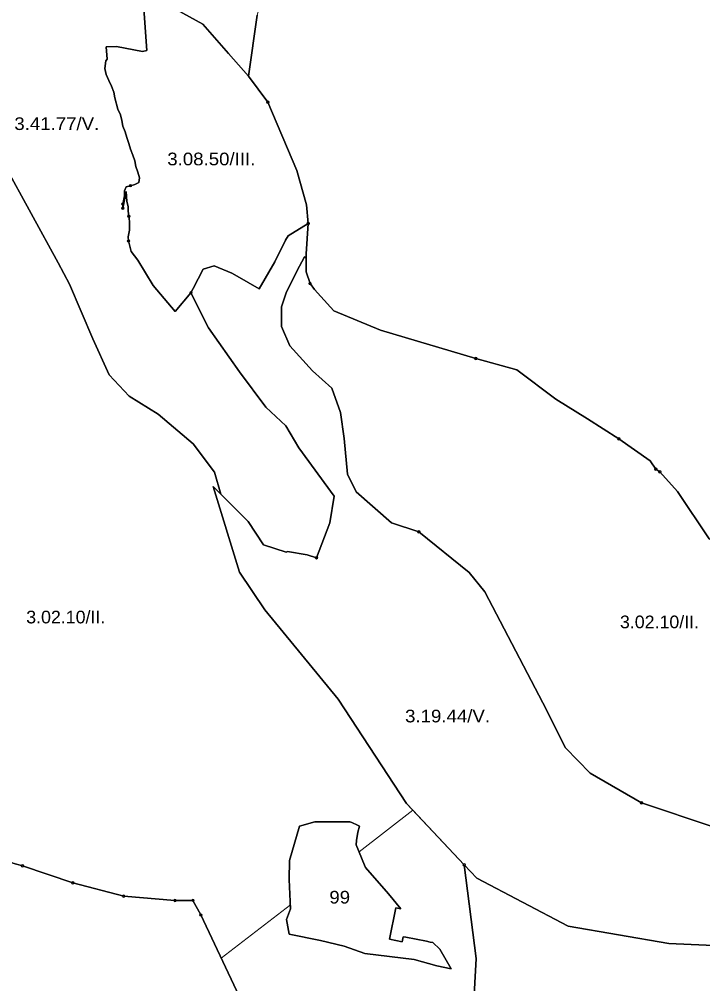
# Model space of a CAD drawing. Extents: x -650455 to -642254, y -1075222 to -1066610.
# Drawn here: x -645923 to -645383, y -1070807 to -1070045 of the extents above; entities that cross this region are included whole.
import ezdxf
from ezdxf.enums import TextEntityAlignment as Align

# ---------------------------------------------------------------- set-up
doc = ezdxf.new("R2010")
doc.units = 0
doc.header["$LTSCALE"] = 4
doc.header["$PDMODE"] = 32
doc.header["$PDSIZE"] = 2
for name, color, linetype, lineweight in [('1', 7, 'Continuous', 25), ('11', 7, 'Continuous', 13), ('12', 7, 'Continuous', 13), ('13', 7, 'Continuous', 13), ('15', 7, 'Continuous', 13), ('16', 7, 'Continuous', 13)]:
    doc.layers.add(name, color=color, linetype=linetype, lineweight=lineweight)
doc.layers.add('2', color=7, linetype='Continuous')

msp = doc.modelspace()

# ---------------------------------------------------------------- linework, layer by layer
at = {"layer": '1'}
for points in [[(-645827.805, -1070170.331), (-645829.232, -1070165.834), (-645830.719, -1070161.367), (-645831.596, -1070156.856), (-645833.216, -1070152.24), (-645834.881, -1070147.654), (-645836.323, -1070143.068), (-645837.765, -1070138.483), (-645839.206, -1070133.897), (-645841.079, -1070129.341), (-645841.912, -1070124.948), (-645842.729, -1070120.556), (-645844.914, -1070115.94), (-645847.337, -1070107.036), (-645848.229, -1070102.643), (-645850.013, -1070097.968), (-645852.064, -1070093.293), (-645854.131, -1070088.618), (-645855.32, -1070084.018), (-645854.309, -1070077.93), (-645853.462, -1070076.604), (-645854.242, -1070066.719), (-645845.918, -1070066.459), (-645825.452, -1070070.498), (-645821.972, -1070069.724), (-645825.17, -1070025.403)], [(-645825.17, -1070025.403), (-645821.972, -1070069.724), (-645825.452, -1070070.498), (-645845.918, -1070066.459), (-645854.242, -1070066.719), (-645853.462, -1070076.604), (-645854.309, -1070077.93), (-645855.32, -1070084.018), (-645854.131, -1070088.618), (-645852.064, -1070093.293), (-645850.013, -1070097.968), (-645848.229, -1070102.643), (-645847.337, -1070107.036), (-645844.914, -1070115.94), (-645842.729, -1070120.556)], [(-645817.043, -1070027.048), (-645777.762, -1070048.899), (-645757.472, -1070072.051), (-645741.915, -1070090.098)], [(-645735.031, -1070041.903), (-645741.915, -1070090.098), (-645757.472, -1070072.051), (-645777.762, -1070048.899), (-645817.043, -1070027.048)], [(-645474.208, -1070360.748), (-645499.088, -1070345.198), (-645530.032, -1070322.029), (-645562.376, -1070313.01), (-645637.482, -1070290.618), (-645674.491, -1070275.223), (-645677.134, -1070272.424), (-645689.807, -1070258.381), (-645693.219, -1070253.691), (-645696.21, -1070244.446), (-645696.21, -1070233.478), (-645696.21, -1070230.279), (-645694.628, -1070206.315), (-645696, -1070191.501), (-645703.5, -1070164.501), (-645726.5, -1070110.501), (-645741.915, -1070090.098), (-645735.031, -1070041.903)], [(-645741.915, -1070090.098), (-645726.5, -1070110.501), (-645703.5, -1070164.501), (-645696, -1070191.501), (-645694.628, -1070206.315), (-645710.517, -1070216.036), (-645712.468, -1070219.418), (-645721.12, -1070236.652), (-645733.239, -1070257.86), (-645750.708, -1070248.033), (-645754.87, -1070245.692), (-645768.918, -1070239.709), (-645777.502, -1070242.31), (-645785.567, -1070257.658), (-645787.196, -1070260.996), (-645799.614, -1070275.867), (-645817.043, -1070255.317), (-645829.113, -1070235.357), (-645831.774, -1070231.886), (-645834.45, -1070228.415), (-645835.52, -1070224.275), (-645836.59, -1070220.135), (-645836.754, -1070216.783), (-645836.218, -1070214.145), (-645835.683, -1070211.506), (-645835.698, -1070204.743), (-645836.248, -1070200.618), (-645836.798, -1070196.493), (-645836.694, -1070192.948), (-645837.839, -1070188.926), (-645838.285, -1070181.137), (-645841.065, -1070194.285), (-645841.065, -1070190.985), (-645839.771, -1070184.475), (-645839.593, -1070180.632), (-645838.3, -1070177.339), (-645834.881, -1070176.492), (-645831.462, -1070175.645), (-645828.37, -1070173.935), (-645827.805, -1070170.331)], [(-645842.729, -1070120.556), (-645841.912, -1070124.948), (-645841.079, -1070129.341), (-645839.206, -1070133.897), (-645837.765, -1070138.483), (-645836.323, -1070143.068), (-645834.881, -1070147.654), (-645833.216, -1070152.24), (-645831.596, -1070156.856), (-645830.719, -1070161.367), (-645829.232, -1070165.834), (-645827.805, -1070170.331), (-645828.37, -1070173.935), (-645831.462, -1070175.645), (-645834.881, -1070176.492), (-645838.3, -1070177.339), (-645839.593, -1070180.632), (-645839.771, -1070184.475), (-645841.065, -1070190.985), (-645841.065, -1070194.285), (-645838.285, -1070181.137), (-645837.839, -1070188.926), (-645836.694, -1070192.948), (-645836.798, -1070196.493), (-645836.248, -1070200.618), (-645835.698, -1070204.743), (-645835.683, -1070211.506), (-645836.218, -1070214.145), (-645836.754, -1070216.783), (-645836.59, -1070220.135), (-645835.52, -1070224.275), (-645834.45, -1070228.415), (-645831.774, -1070231.886), (-645829.113, -1070235.357), (-645817.043, -1070255.317), (-645799.614, -1070275.867), (-645787.196, -1070260.996), (-645773.285, -1070288.817), (-645748.941, -1070323.593), (-645728.075, -1070351.415)], [(-645937.054, -1070142.706), (-645934.808, -1070159.546), (-645892.146, -1070237.292), (-645883.165, -1070254.133), (-645864.64, -1070297.356), (-645851.729, -1070325.985), (-645836.012, -1070342.825), (-645812.997, -1070356.859), (-645785.491, -1070380.435), (-645768.65, -1070402.889), (-645763.626, -1070420.193)], [(-645728.075, -1070351.415), (-645712.426, -1070366.195), (-645701.993, -1070383.583), (-645674.172, -1070421.837), (-645677.649, -1070442.703), (-645688.022, -1070470.362), (-645695.5, -1070468.001), (-645711, -1070465.5), (-645712.054, -1070466.012), (-645729.814, -1070460.091), (-645741.986, -1070441.834), (-645763.626, -1070420.193), (-645768.65, -1070402.889), (-645785.491, -1070380.435), (-645812.997, -1070356.859), (-645836.012, -1070342.825), (-645851.729, -1070325.985), (-645864.64, -1070297.356), (-645883.165, -1070254.133), (-645892.146, -1070237.292), (-645934.808, -1070159.546)], [(-645749.009, -1070481.878), (-645769.807, -1070414.012), (-645763.626, -1070420.193), (-645741.986, -1070441.834), (-645729.814, -1070460.091), (-645712.054, -1070466.012), (-645711, -1070465.5), (-645695.5, -1070468.001), (-645688.022, -1070470.362), (-645677.649, -1070442.703), (-645674.172, -1070421.837), (-645701.993, -1070383.583), (-645712.426, -1070366.195), (-645728.075, -1070351.415), (-645748.941, -1070323.593), (-645773.285, -1070288.817), (-645787.196, -1070260.996), (-645785.567, -1070257.658), (-645777.502, -1070242.31), (-645768.918, -1070239.709), (-645754.87, -1070245.692), (-645750.708, -1070248.033), (-645733.239, -1070257.86), (-645721.12, -1070236.652), (-645712.468, -1070219.418), (-645710.517, -1070216.036), (-645694.628, -1070206.315), (-645696.21, -1070230.279), (-645696.21, -1070233.478)], [(-645696.21, -1070233.478), (-645697.505, -1070232.772), (-645703.725, -1070244.123), (-645712.121, -1070261.228), (-645715.698, -1070272.269), (-645715.698, -1070287.819), (-645709.167, -1070303.058), (-645691.285, -1070322.806), (-645676.046, -1070336.49), (-645669.048, -1070355.616), (-645666.347, -1070376.193), (-645663.739, -1070404.449), (-645656.783, -1070418.36), (-645628.962, -1070442.703), (-645607.333, -1070449.913), (-645567.5, -1070482), (-645555.128, -1070497.341), (-645509.5, -1070585.001), (-645491.5, -1070620.501), (-645472, -1070640.5), (-645431.5, -1070664), (-645375, -1070683.001)], [(-645656.783, -1070418.36), (-645663.739, -1070404.449), (-645666.347, -1070376.193), (-645669.048, -1070355.616), (-645676.046, -1070336.49), (-645691.285, -1070322.806), (-645709.167, -1070303.058), (-645715.698, -1070287.819), (-645715.698, -1070272.269), (-645712.121, -1070261.228), (-645703.725, -1070244.123), (-645697.505, -1070232.772), (-645696.21, -1070233.478)], [(-645696.21, -1070233.478), (-645696.21, -1070244.446), (-645693.219, -1070253.691), (-645689.807, -1070258.381), (-645677.134, -1070272.424), (-645674.491, -1070275.223), (-645637.482, -1070290.618), (-645562.376, -1070313.01), (-645530.032, -1070322.029), (-645499.088, -1070345.198), (-645474.208, -1070360.748), (-645449.328, -1070376.453), (-645424.604, -1070393.714), (-645420.219, -1070400.367), (-645417, -1070402.501), (-645403, -1070418.001), (-645378, -1070455.501)], [(-644832, -1070537.001), (-644888.5, -1070557.001), (-644982, -1070577.501), (-645008.5, -1070579.5), (-645087, -1070571), (-645188.5, -1070544.501), (-645235, -1070537.001), (-645245, -1070532.501), (-645282.5, -1070523), (-645302, -1070515.501), (-645378, -1070455.501), (-645403, -1070418.001), (-645417, -1070402.501), (-645420.219, -1070400.367), (-645424.604, -1070393.714), (-645449.328, -1070376.453), (-645474.208, -1070360.748)], [(-645763.626, -1070420.193), (-645769.807, -1070414.012), (-645749.009, -1070481.878), (-645729, -1070511.501), (-645671, -1070582), (-645617, -1070664.5), (-645571.435, -1070712.939), (-645562, -1070787.001), (-645566, -1070859), (-645576.5, -1070881.501), (-645600.5, -1070904.001), (-645607.5, -1070909.001), (-645646.5, -1070921.501), (-645665, -1070920), (-645678.5, -1070914.5), (-645700.5, -1070899.5), (-645723, -1070872.001), (-645779.5, -1070752.5), (-645785.632, -1070741.019), (-645799.865, -1070741.1), (-645840.313, -1070737.642), (-645880.438, -1070727.108), (-645920.242, -1070713.679), (-645927.962, -1070711.588)], [(-645375, -1070683.001), (-645431.5, -1070664), (-645472, -1070640.5), (-645491.5, -1070620.501), (-645509.5, -1070585.001), (-645555.128, -1070497.341), (-645567.5, -1070482), (-645607.333, -1070449.913), (-645628.962, -1070442.703), (-645656.783, -1070418.36)], [(-645368.5, -1070777), (-645410, -1070775.001), (-645489.5, -1070761.5), (-645561.5, -1070723.501), (-645571.435, -1070712.939), (-645617, -1070664.5), (-645671, -1070582), (-645729, -1070511.501), (-645749.009, -1070481.878)], [(-645566, -1070859), (-645562, -1070787.001), (-645571.435, -1070712.939), (-645561.5, -1070723.501), (-645489.5, -1070761.5), (-645410, -1070775.001), (-645368.5, -1070777), (-645281.5, -1070761.5), (-645208.5, -1070763.501), (-645185.5, -1070754), (-645181.5, -1070740), (-645182, -1070713), (-645200.205, -1070663.392), (-645202, -1070658.501), (-645195.5, -1070648), (-645179.5, -1070600), (-645179.5, -1070566.5), (-645188.5, -1070544.501), (-645087, -1070571), (-645008.5, -1070579.5), (-644982, -1070577.501), (-644888.5, -1070557.001), (-644832, -1070537.001)], [(-645927.962, -1070711.588), (-645920.242, -1070713.679), (-645880.438, -1070727.108), (-645840.313, -1070737.642)], [(-645840.313, -1070737.642), (-645799.865, -1070741.1), (-645785.632, -1070741.019), (-645779.5, -1070752.5), (-645723, -1070872.001)]]:
    msp.add_lwpolyline(points, dxfattribs=at)
for points in [[(-645631.348, -1070735.807), (-645621.58, -1070747.558), (-645625.53, -1070746.79), (-645630.39, -1070771.751), (-645620.35, -1070773.691), (-645619.59, -1070769.75), (-645617.65, -1070770.131), (-645601.26, -1070773.33), (-645598.31, -1070773.9), (-645596.319, -1070774.289), (-645590.68, -1070779.525), (-645581.869, -1070795.114), (-645593.052, -1070792.742), (-645611.014, -1070787.659), (-645649.987, -1070782.914), (-645666.254, -1070777.153), (-645684.894, -1070772.747), (-645709.633, -1070767.664), (-645711.667, -1070756.141), (-645708.617, -1070747.669), (-645709.633, -1070724.623), (-645709.294, -1070709.373), (-645701.5, -1070682.261), (-645689.299, -1070678.872), (-645661.848, -1070678.872), (-645660.211, -1070679.584), (-645660.21, -1070679.591), (-645655.86, -1070681.476), (-645654.054, -1070682.261), (-645655.409, -1070687.006), (-645656.426, -1070693.784), (-645656.765, -1070697.173), (-645650.141, -1070713.131), (-645650.14, -1070713.14), (-645649.309, -1070715.132)], [(-645631.348, -1070735.807), (-645649.309, -1070715.132), (-645650.14, -1070713.14), (-645650.141, -1070713.131), (-645656.765, -1070697.173), (-645656.426, -1070693.784), (-645655.409, -1070687.006), (-645654.054, -1070682.261), (-645655.86, -1070681.476), (-645660.21, -1070679.591), (-645660.211, -1070679.584), (-645661.848, -1070678.872), (-645689.299, -1070678.872), (-645701.5, -1070682.261), (-645709.294, -1070709.373), (-645709.633, -1070724.623), (-645708.617, -1070747.669), (-645711.667, -1070756.141), (-645709.633, -1070767.664), (-645684.894, -1070772.747), (-645666.254, -1070777.153), (-645649.987, -1070782.914), (-645611.014, -1070787.659), (-645593.052, -1070792.742), (-645581.869, -1070795.114), (-645590.68, -1070779.525), (-645596.319, -1070774.289), (-645598.31, -1070773.9), (-645601.26, -1070773.33), (-645617.65, -1070770.131), (-645619.59, -1070769.75), (-645620.35, -1070773.691), (-645630.39, -1070771.751), (-645625.53, -1070746.79), (-645621.58, -1070747.558)]]:
    msp.add_lwpolyline(points, close=True, dxfattribs=at)
at = {"layer": '11'}
for p, q in [((-645840.313, -1070737.642), (-645880.438, -1070727.108)), ((-645779.5, -1070752.5), (-645785.632, -1070741.019)), ((-645723, -1070872.001), (-645779.5, -1070752.5))]:
    msp.add_line(p, q, dxfattribs=at)
for points in [[(-645725.467, -1069844.112), (-645715.034, -1069885.843), (-645715.034, -1069948.441), (-645711.556, -1069990.173), (-645714.013, -1070000), (-645715.034, -1070004.084), (-645728.075, -1070017.56), (-645735.031, -1070041.903), (-645741.915, -1070090.098), (-645726.5, -1070110.501), (-645703.5, -1070164.501), (-645696, -1070191.501), (-645694.628, -1070206.315), (-645696.21, -1070230.279), (-645696.21, -1070233.478), (-645696.21, -1070244.446), (-645693.219, -1070253.691)], [(-645693.219, -1070253.691), (-645689.807, -1070258.381), (-645677.134, -1070272.424), (-645674.491, -1070275.223), (-645637.482, -1070290.618), (-645562.376, -1070313.01), (-645530.032, -1070322.029), (-645499.088, -1070345.198)], [(-645499.088, -1070345.198), (-645474.208, -1070360.748), (-645449.328, -1070376.453)], [(-645449.328, -1070376.453), (-645424.604, -1070393.714), (-645420.219, -1070400.367), (-645417, -1070402.501)], [(-645417, -1070402.501), (-645403, -1070418.001), (-645378, -1070455.501)], [(-645880.438, -1070727.108), (-645920.242, -1070713.679), (-645927.962, -1070711.588)], [(-645185.5, -1070754), (-645208.5, -1070763.501), (-645281.5, -1070761.5), (-645368.5, -1070777), (-645410, -1070775.001), (-645489.5, -1070761.5), (-645561.5, -1070723.501), (-645571.435, -1070712.939), (-645562, -1070787.001), (-645566, -1070859), (-645576.5, -1070881.501), (-645600.5, -1070904.001), (-645607.5, -1070909.001), (-645646.5, -1070921.501), (-645665, -1070920), (-645678.5, -1070914.5), (-645700.5, -1070899.5)], [(-645785.632, -1070741.019), (-645799.865, -1070741.1), (-645840.313, -1070737.642)]]:
    msp.add_lwpolyline(points, dxfattribs=at)
for p in [(-645693.219, -1070253.691), (-645449.328, -1070376.453), (-645417, -1070402.501), (-645880.438, -1070727.108), (-645840.313, -1070737.642), (-645785.632, -1070741.019), (-645779.5, -1070752.5)]:
    msp.add_point(p, dxfattribs=at)
at = {"layer": '12'}
msp.add_line((-645920.242, -1070713.679), (-645880.438, -1070727.108), dxfattribs=at)
for points in [[(-645850.5, -1069989.001), (-645845.117, -1070000), (-645839, -1070012.5), (-645829.689, -1070021.439), (-645826.5, -1070024.5), (-645825.17, -1070025.403), (-645817.043, -1070027.048), (-645777.762, -1070048.899), (-645757.472, -1070072.051), (-645741.915, -1070090.098), (-645735.031, -1070041.903), (-645728.075, -1070017.56), (-645715.034, -1070004.084)], [(-645660.21, -1070679.591), (-645655.86, -1070681.476), (-645654.054, -1070682.261), (-645655.409, -1070687.006), (-645656.426, -1070693.784), (-645656.765, -1070697.173), (-645654.518, -1070702.587), (-645612.056, -1070669.756), (-645617, -1070664.5), (-645671, -1070582), (-645729, -1070511.501), (-645749.009, -1070481.878), (-645769.807, -1070414.012), (-645763.626, -1070420.193), (-645768.65, -1070402.889), (-645785.491, -1070380.435), (-645812.997, -1070356.859), (-645836.012, -1070342.825), (-645851.729, -1070325.985), (-645864.64, -1070297.356), (-645883.165, -1070254.133), (-645892.146, -1070237.292), (-645934.808, -1070159.546)], [(-645562.376, -1070313.01), (-645637.482, -1070290.618), (-645674.491, -1070275.223), (-645677.134, -1070272.424), (-645689.807, -1070258.381), (-645693.219, -1070253.691), (-645696.21, -1070244.446), (-645696.21, -1070233.478), (-645697.505, -1070232.772), (-645703.725, -1070244.123), (-645712.121, -1070261.228), (-645715.698, -1070272.269), (-645715.698, -1070287.819), (-645709.167, -1070303.058), (-645691.285, -1070322.806), (-645676.046, -1070336.49), (-645669.048, -1070355.616), (-645666.347, -1070376.193), (-645663.739, -1070404.449), (-645656.783, -1070418.36), (-645628.962, -1070442.703), (-645607.333, -1070449.913)], [(-645420.219, -1070400.367), (-645424.604, -1070393.714), (-645449.328, -1070376.453), (-645474.208, -1070360.748), (-645499.088, -1070345.198), (-645530.032, -1070322.029), (-645562.376, -1070313.01)], [(-645195.5, -1070648), (-645179.5, -1070600), (-645179.5, -1070566.5), (-645188.5, -1070544.501), (-645235, -1070537.001), (-645245, -1070532.501), (-645282.5, -1070523), (-645302, -1070515.501), (-645378, -1070455.501), (-645403, -1070418.001), (-645417, -1070402.501), (-645420.219, -1070400.367)], [(-645607.333, -1070449.913), (-645567.5, -1070482), (-645555.128, -1070497.341), (-645509.5, -1070585.001), (-645491.5, -1070620.501), (-645472, -1070640.5), (-645431.5, -1070664)], [(-645982.884, -1070639.297), (-645972.912, -1070658.757), (-645965.032, -1070672.106), (-645950.317, -1070694.38), (-645927.962, -1070711.588), (-645920.242, -1070713.679)], [(-645431.5, -1070664), (-645375, -1070683.001), (-645345.5, -1070688.5), (-645317, -1070688), (-645234.5, -1070674.001), (-645200.205, -1070663.392)], [(-645566, -1070859), (-645562, -1070787.001), (-645571.435, -1070712.939), (-645612.056, -1070669.756), (-645654.518, -1070702.587), (-645650.141, -1070713.131), (-645650.14, -1070713.14), (-645649.309, -1070715.132), (-645631.348, -1070735.807), (-645621.58, -1070747.558), (-645625.53, -1070746.79), (-645630.39, -1070771.751), (-645620.35, -1070773.691), (-645619.59, -1070769.75), (-645617.65, -1070770.131), (-645601.26, -1070773.33), (-645598.31, -1070773.9), (-645596.319, -1070774.289), (-645590.68, -1070779.525), (-645581.869, -1070795.114), (-645593.052, -1070792.742), (-645611.014, -1070787.659), (-645649.987, -1070782.914), (-645666.254, -1070777.153), (-645684.894, -1070772.747), (-645709.633, -1070767.664), (-645711.667, -1070756.141), (-645708.617, -1070747.669), (-645708.756, -1070744.522), (-645763.324, -1070786.713), (-645723, -1070872.001)], [(-645799.865, -1070741.1), (-645785.632, -1070741.019), (-645779.5, -1070752.5), (-645763.324, -1070786.713), (-645708.756, -1070744.522), (-645709.633, -1070724.623), (-645709.294, -1070709.373), (-645701.5, -1070682.261), (-645689.299, -1070678.872), (-645661.848, -1070678.872), (-645660.211, -1070679.584)], [(-645880.438, -1070727.108), (-645840.313, -1070737.642), (-645799.865, -1070741.1)]]:
    msp.add_lwpolyline(points, dxfattribs=at)
for p in [(-645562.376, -1070313.01), (-645420.219, -1070400.367), (-645607.333, -1070449.913), (-645431.5, -1070664), (-645920.242, -1070713.679), (-645880.438, -1070727.108), (-645799.865, -1070741.1)]:
    msp.add_point(p, dxfattribs=at)
at = {"layer": '13'}
for points in [[(-645825.17, -1070025.403), (-645821.972, -1070069.724), (-645825.452, -1070070.498), (-645845.918, -1070066.459), (-645854.242, -1070066.719), (-645853.462, -1070076.604), (-645854.309, -1070077.93), (-645855.32, -1070084.018), (-645854.131, -1070088.618), (-645852.064, -1070093.293), (-645850.013, -1070097.968), (-645848.229, -1070102.643), (-645847.337, -1070107.036), (-645844.914, -1070115.94), (-645842.729, -1070120.556), (-645841.912, -1070124.948), (-645841.079, -1070129.341), (-645839.206, -1070133.897), (-645837.765, -1070138.483), (-645836.323, -1070143.068), (-645834.881, -1070147.654), (-645833.216, -1070152.24), (-645831.596, -1070156.856), (-645830.719, -1070161.367), (-645829.232, -1070165.834), (-645827.805, -1070170.331), (-645828.37, -1070173.935), (-645831.462, -1070175.645), (-645834.881, -1070176.492), (-645838.3, -1070177.339), (-645839.593, -1070180.632), (-645839.771, -1070184.475), (-645841.065, -1070190.985), (-645841.065, -1070194.285)], [(-645726.5, -1070110.501), (-645741.915, -1070090.098), (-645757.472, -1070072.051), (-645777.762, -1070048.899), (-645817.043, -1070027.048)], [(-645694.628, -1070206.315), (-645696, -1070191.501), (-645703.5, -1070164.501), (-645726.5, -1070110.501)], [(-645841.065, -1070194.285), (-645838.285, -1070181.137), (-645837.839, -1070188.926), (-645836.694, -1070192.948), (-645836.798, -1070196.493), (-645836.248, -1070200.618), (-645835.698, -1070204.743), (-645835.683, -1070211.506), (-645836.218, -1070214.145), (-645836.754, -1070216.783), (-645836.59, -1070220.135)], [(-645787.196, -1070260.996), (-645785.567, -1070257.658), (-645777.502, -1070242.31), (-645768.918, -1070239.709), (-645754.87, -1070245.692), (-645750.708, -1070248.033), (-645733.239, -1070257.86), (-645721.12, -1070236.652), (-645712.468, -1070219.418), (-645710.517, -1070216.036), (-645694.628, -1070206.315)], [(-645836.59, -1070220.135), (-645835.52, -1070224.275), (-645834.45, -1070228.415), (-645831.774, -1070231.886), (-645829.113, -1070235.357), (-645817.043, -1070255.317), (-645799.614, -1070275.867), (-645787.196, -1070260.996)]]:
    msp.add_lwpolyline(points, dxfattribs=at)
for p in [(-645726.5, -1070110.501), (-645841.065, -1070194.285), (-645694.628, -1070206.315), (-645836.59, -1070220.135), (-645787.196, -1070260.996)]:
    msp.add_point(p, dxfattribs=at)
at = {"layer": '15'}
for points in [[(-645834.881, -1070176.492), (-645831.462, -1070175.645), (-645828.37, -1070173.935), (-645827.805, -1070170.331), (-645829.232, -1070165.834), (-645830.719, -1070161.367), (-645831.596, -1070156.856), (-645833.216, -1070152.24), (-645834.881, -1070147.654), (-645836.323, -1070143.068), (-645837.765, -1070138.483), (-645839.206, -1070133.897), (-645841.079, -1070129.341), (-645841.912, -1070124.948), (-645842.729, -1070120.556), (-645844.914, -1070115.94), (-645847.337, -1070107.036), (-645848.229, -1070102.643), (-645850.013, -1070097.968), (-645852.064, -1070093.293), (-645854.131, -1070088.618), (-645855.32, -1070084.018), (-645854.309, -1070077.93), (-645853.462, -1070076.604), (-645854.242, -1070066.719), (-645845.918, -1070066.459), (-645825.452, -1070070.498), (-645821.972, -1070069.724), (-645825.17, -1070025.403)], [(-645949.403, -1070096.114), (-645949.965, -1070116.884), (-645937.054, -1070142.706), (-645934.808, -1070159.546), (-645892.146, -1070237.292), (-645883.165, -1070254.133), (-645864.64, -1070297.356), (-645851.729, -1070325.985), (-645836.012, -1070342.825), (-645812.997, -1070356.859), (-645785.491, -1070380.435), (-645768.65, -1070402.889), (-645763.626, -1070420.193), (-645741.986, -1070441.834), (-645729.814, -1070460.091), (-645712.054, -1070466.012), (-645711, -1070465.5), (-645695.5, -1070468.001), (-645688.022, -1070470.362)], [(-645841.065, -1070190.985), (-645839.771, -1070184.475), (-645839.593, -1070180.632), (-645838.3, -1070177.339), (-645834.881, -1070176.492)], [(-645836.248, -1070200.618), (-645836.798, -1070196.493), (-645836.694, -1070192.948), (-645837.839, -1070188.926), (-645838.285, -1070181.137), (-645841.065, -1070194.285), (-645841.065, -1070190.985)], [(-645688.022, -1070470.362), (-645677.649, -1070442.703), (-645674.172, -1070421.837), (-645701.993, -1070383.583), (-645712.426, -1070366.195), (-645728.075, -1070351.415), (-645748.941, -1070323.593), (-645773.285, -1070288.817), (-645787.196, -1070260.996), (-645799.614, -1070275.867), (-645817.043, -1070255.317), (-645829.113, -1070235.357), (-645831.774, -1070231.886), (-645834.45, -1070228.415), (-645835.52, -1070224.275), (-645836.59, -1070220.135), (-645836.754, -1070216.783), (-645836.218, -1070214.145), (-645835.683, -1070211.506), (-645835.698, -1070204.743), (-645836.248, -1070200.618)], [(-645375, -1070683.001), (-645431.5, -1070664), (-645472, -1070640.5), (-645491.5, -1070620.501), (-645509.5, -1070585.001), (-645555.128, -1070497.341), (-645567.5, -1070482), (-645607.333, -1070449.913), (-645628.962, -1070442.703), (-645656.783, -1070418.36), (-645663.739, -1070404.449), (-645666.347, -1070376.193), (-645669.048, -1070355.616), (-645676.046, -1070336.49), (-645691.285, -1070322.806), (-645709.167, -1070303.058), (-645715.698, -1070287.819), (-645715.698, -1070272.269), (-645712.121, -1070261.228), (-645703.725, -1070244.123), (-645697.505, -1070232.772), (-645696.21, -1070233.478), (-645696.21, -1070230.279), (-645694.628, -1070206.315), (-645710.517, -1070216.036), (-645712.468, -1070219.418), (-645721.12, -1070236.652), (-645733.239, -1070257.86), (-645750.708, -1070248.033), (-645754.87, -1070245.692), (-645768.918, -1070239.709), (-645777.502, -1070242.31), (-645785.567, -1070257.658), (-645787.196, -1070260.996)], [(-645787.196, -1070260.996), (-645773.285, -1070288.817), (-645748.941, -1070323.593), (-645728.075, -1070351.415), (-645712.426, -1070366.195), (-645701.993, -1070383.583), (-645674.172, -1070421.837), (-645677.649, -1070442.703), (-645688.022, -1070470.362), (-645695.5, -1070468.001), (-645711, -1070465.5), (-645712.054, -1070466.012), (-645729.814, -1070460.091), (-645741.986, -1070441.834), (-645763.626, -1070420.193), (-645769.807, -1070414.012), (-645749.009, -1070481.878), (-645729, -1070511.501), (-645671, -1070582), (-645617, -1070664.5), (-645616.574, -1070664.953), (-645612.056, -1070669.756), (-645571.435, -1070712.939)], [(-645571.435, -1070712.939), (-645561.5, -1070723.501), (-645489.5, -1070761.5), (-645410, -1070775.001), (-645368.5, -1070777), (-645281.5, -1070761.5)]]:
    msp.add_lwpolyline(points, dxfattribs=at)
for p in [(-645834.881, -1070176.492), (-645841.065, -1070190.985), (-645836.248, -1070200.618), (-645787.196, -1070260.996), (-645688.022, -1070470.362), (-645571.435, -1070712.939)]:
    msp.add_point(p, dxfattribs=at)
at = {"layer": '16'}
msp.add_line((-645709.633, -1070767.664), (-645694.241, -1070770.826), dxfattribs=at)
msp.add_lwpolyline([(-645694.241, -1070770.826), (-645684.894, -1070772.747), (-645666.254, -1070777.153), (-645649.987, -1070782.914), (-645611.014, -1070787.659), (-645593.052, -1070792.742), (-645581.869, -1070795.114), (-645590.68, -1070779.525), (-645596.319, -1070774.289), (-645598.31, -1070773.9), (-645601.26, -1070773.33), (-645617.65, -1070770.131), (-645619.59, -1070769.75), (-645620.35, -1070773.691), (-645630.39, -1070771.751), (-645625.53, -1070746.79), (-645621.58, -1070747.558), (-645631.348, -1070735.807), (-645649.309, -1070715.132), (-645650.14, -1070713.14), (-645650.141, -1070713.131), (-645650.189, -1070713.015), (-645654.518, -1070702.587), (-645656.765, -1070697.173), (-645656.426, -1070693.784), (-645655.409, -1070687.006), (-645654.054, -1070682.261), (-645655.86, -1070681.476), (-645660.21, -1070679.591), (-645660.211, -1070679.584), (-645661.848, -1070678.872), (-645689.299, -1070678.872), (-645701.5, -1070682.261), (-645709.294, -1070709.373), (-645709.633, -1070724.623), (-645708.756, -1070744.522), (-645708.635, -1070747.252), (-645708.617, -1070747.669), (-645711.667, -1070756.141), (-645709.633, -1070767.664)], dxfattribs=at)

# ---------------------------------------------------------------- texts
at = {"layer": '2'}
for s, width, p in [('3.41.77/V.', 1.1, (-645893.136, -1070132.488)), ('3.08.50/III.', 1.1, (-645771.14, -1070160.379)), ('3.02.10/II.', 1.05, (-645886.055, -1070522.198)), ('3.02.10/II.', 1.05, (-645417.306, -1070526.048)), ('3.19.44/V.', 1.1, (-645584.628, -1070600.39)), ('99', 1.1, (-645669.775, -1070743.491))]:
    msp.add_text(s, height=10, dxfattribs=dict(at, width=width)).set_placement(p, align=Align.CENTER)

doc.saveas('drawing.dxf')
